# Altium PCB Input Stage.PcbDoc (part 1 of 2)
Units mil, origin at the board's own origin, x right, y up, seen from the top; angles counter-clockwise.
Board outline 5000 x 8750 mil, 6 copper layers (Top Layer, Layer 1, Layer 2, Layer 3, Layer 4, Bottom Layer), stack 91 mil thick; 55 components, 34 nets, 272 pads, 68 vias.
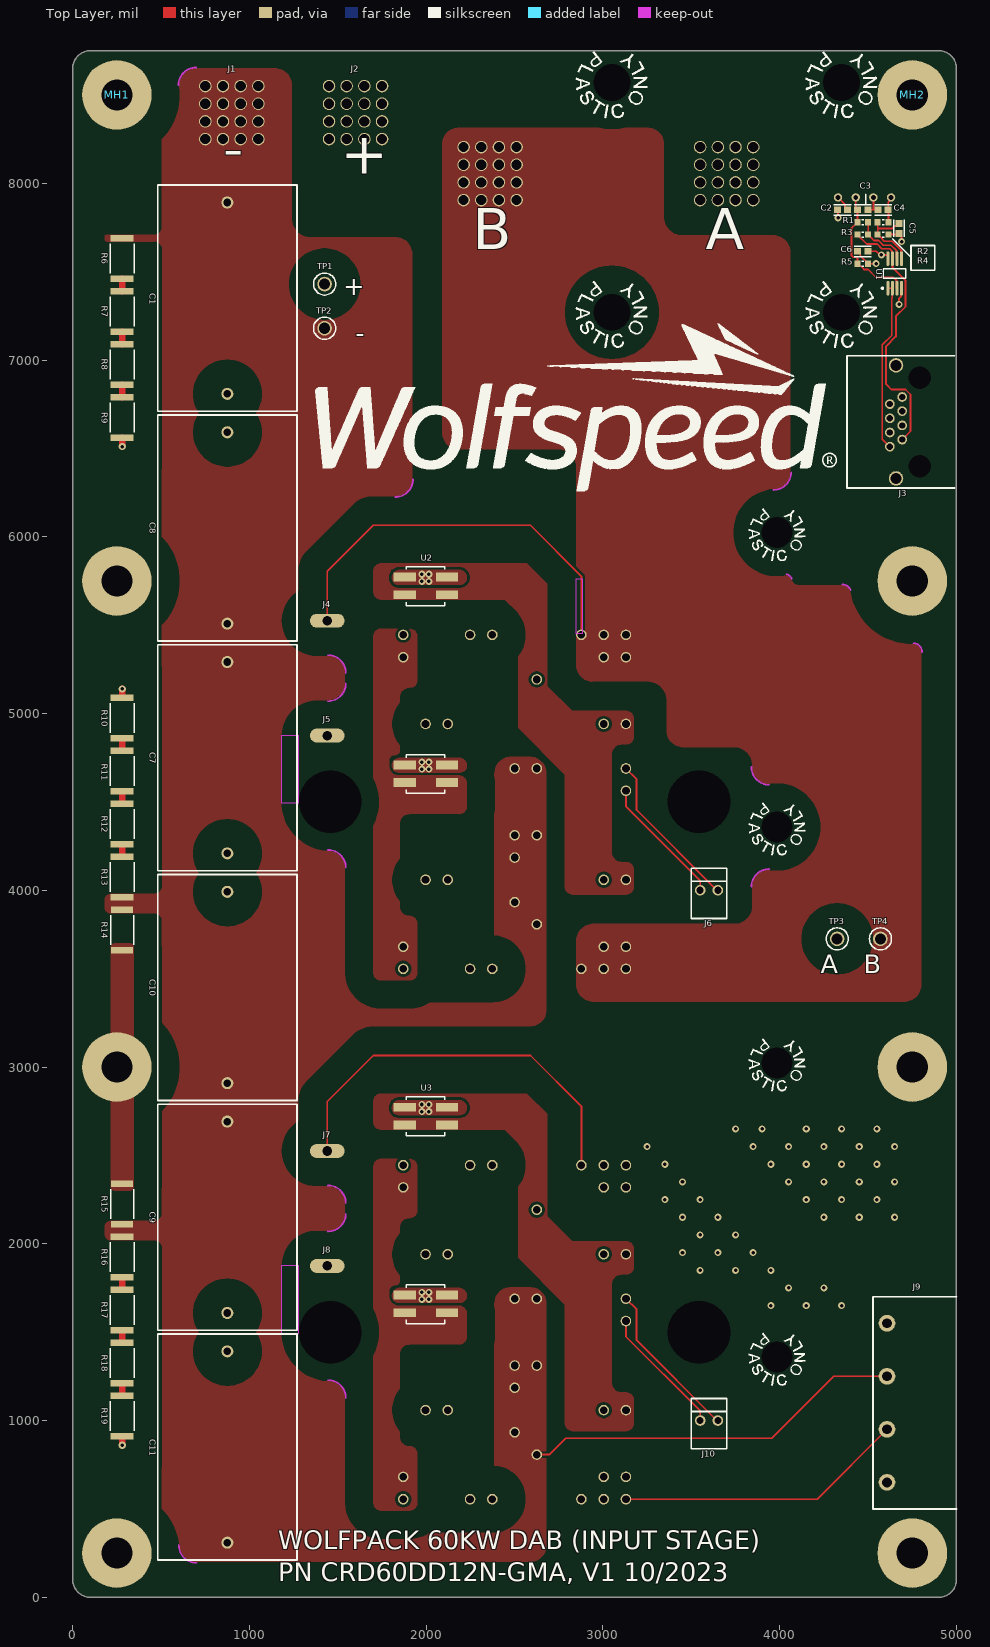
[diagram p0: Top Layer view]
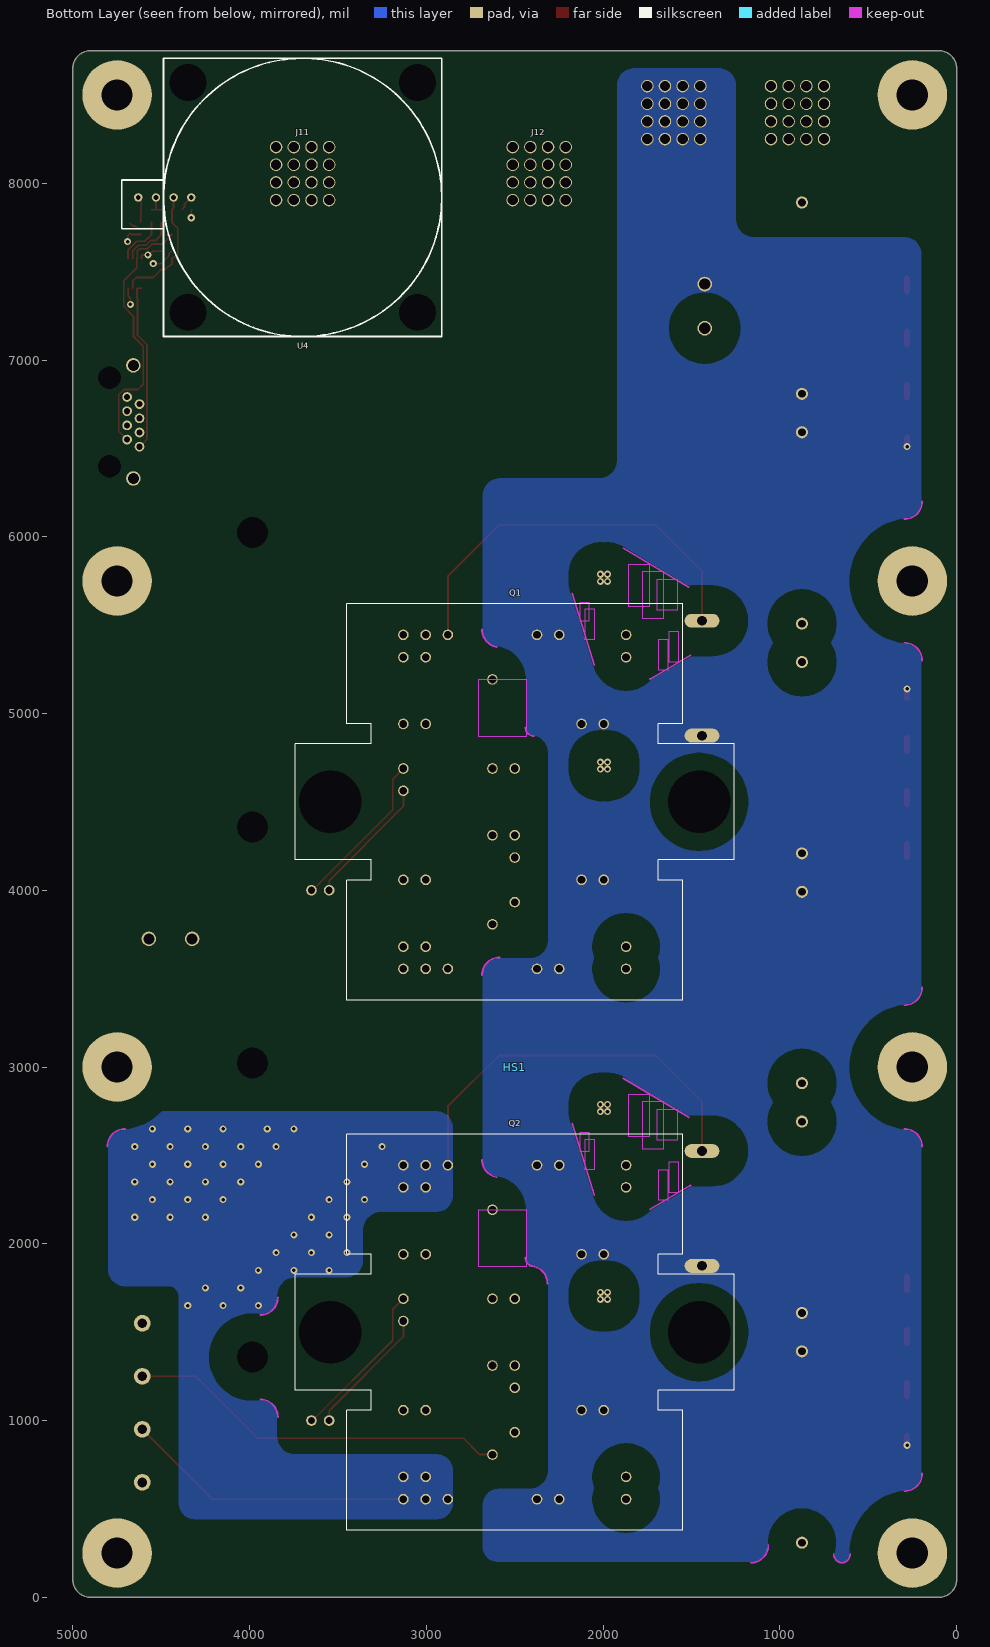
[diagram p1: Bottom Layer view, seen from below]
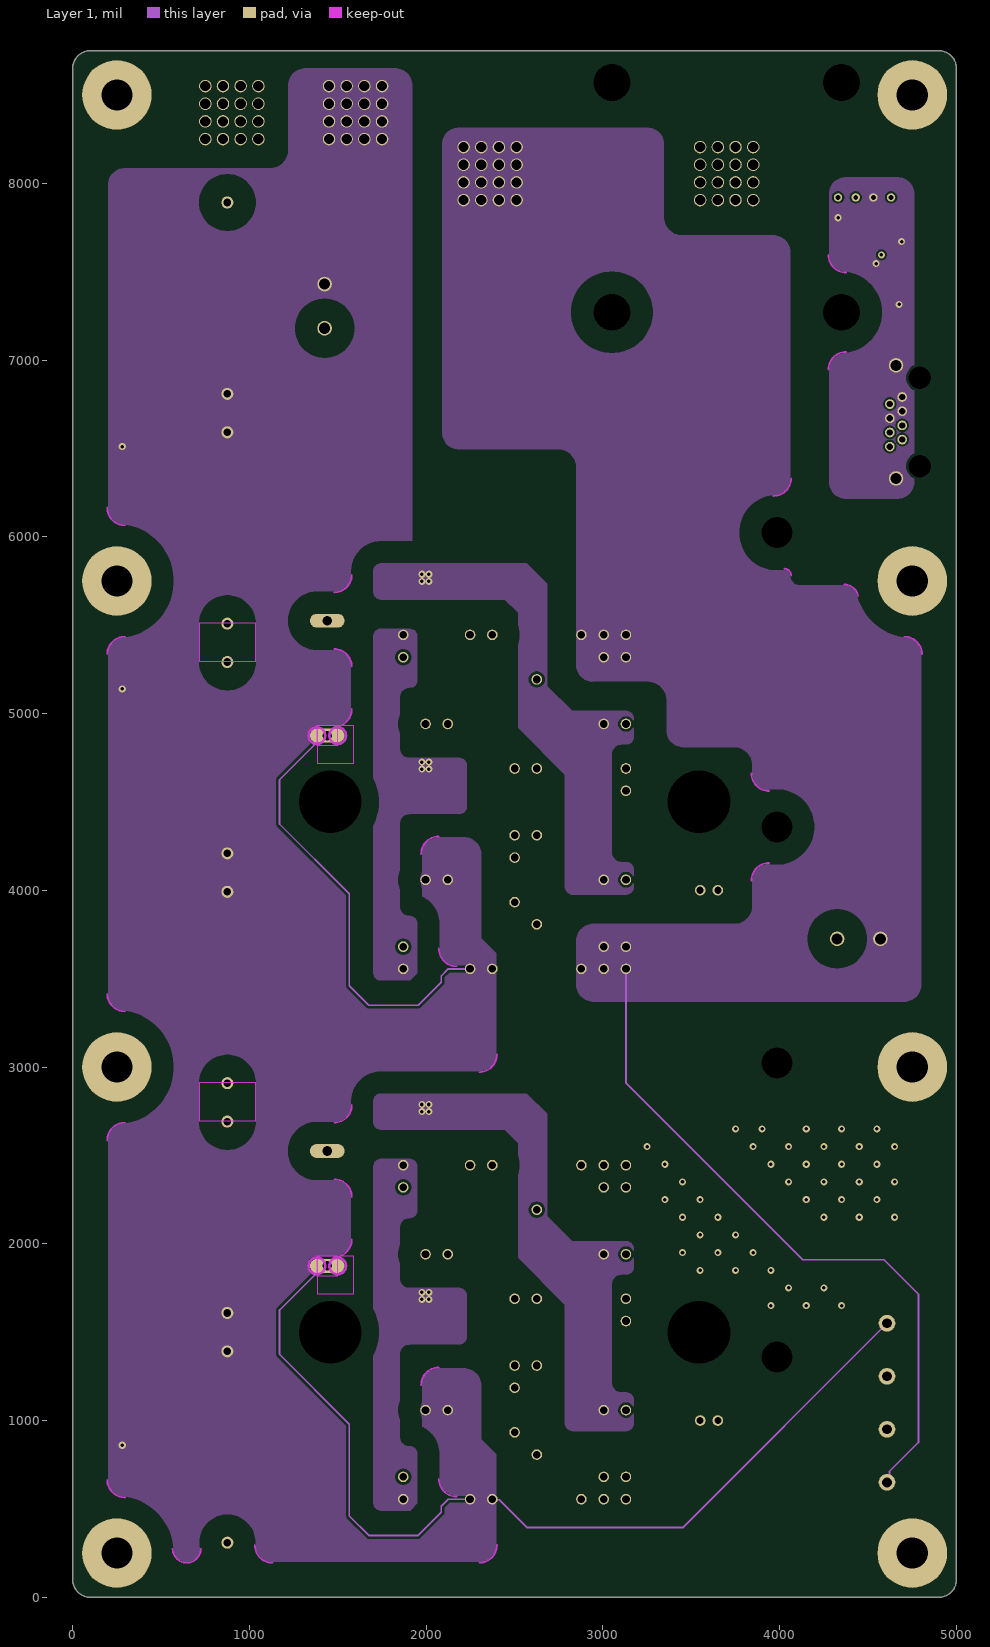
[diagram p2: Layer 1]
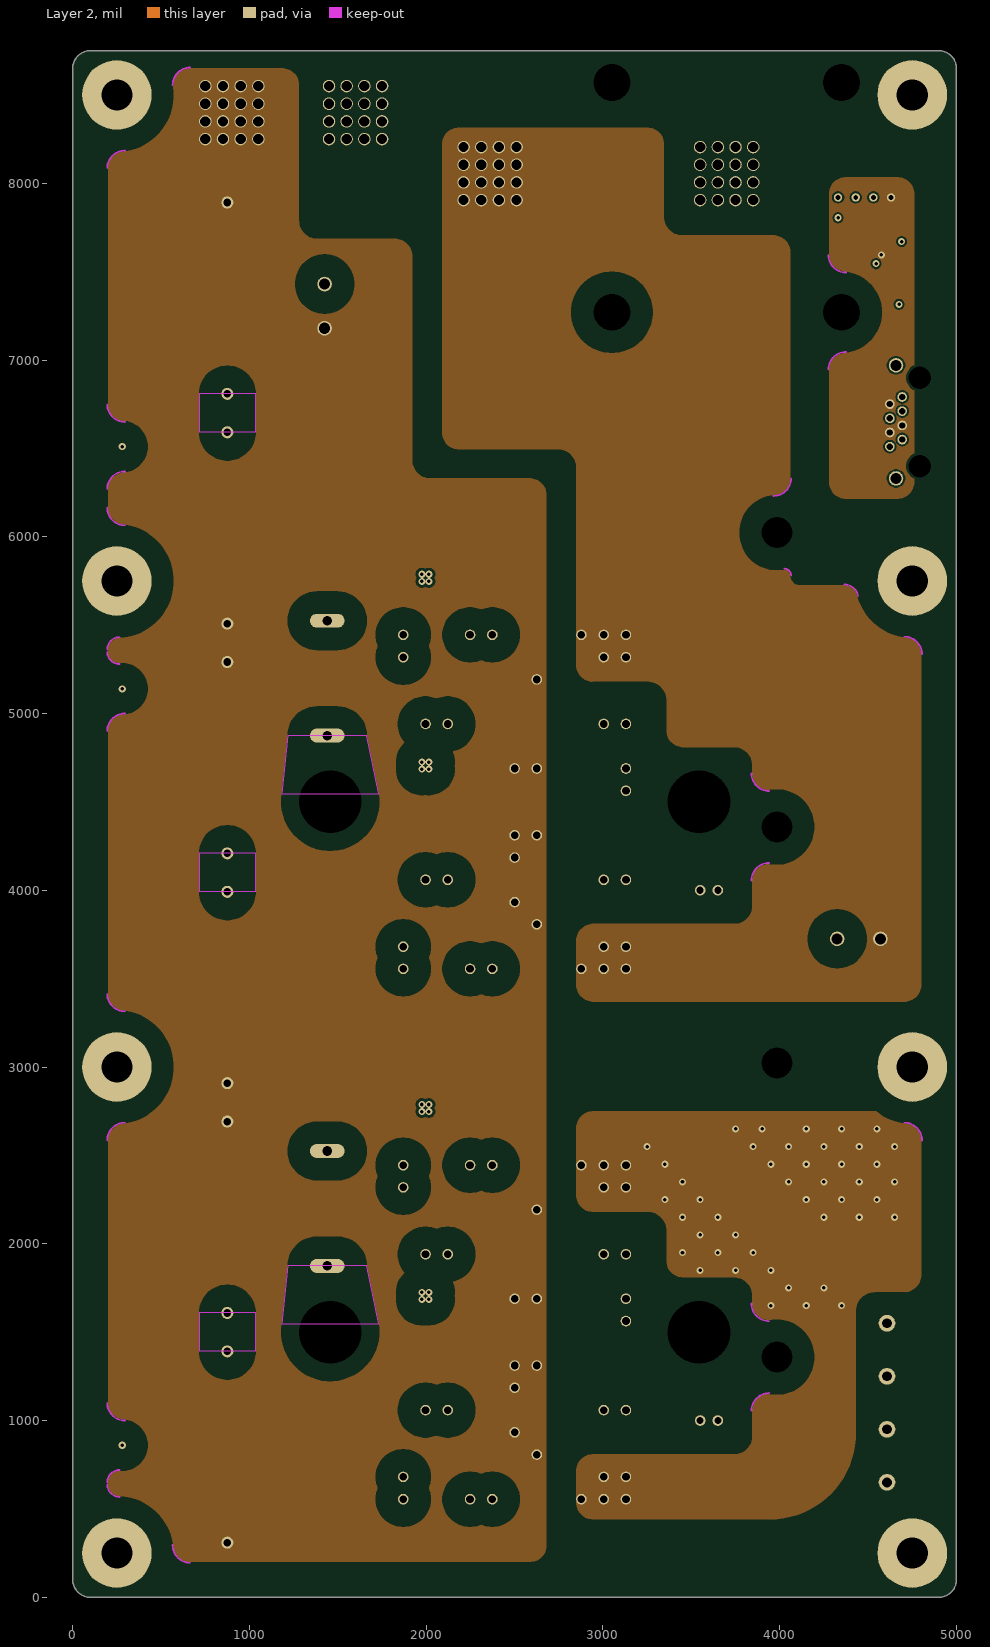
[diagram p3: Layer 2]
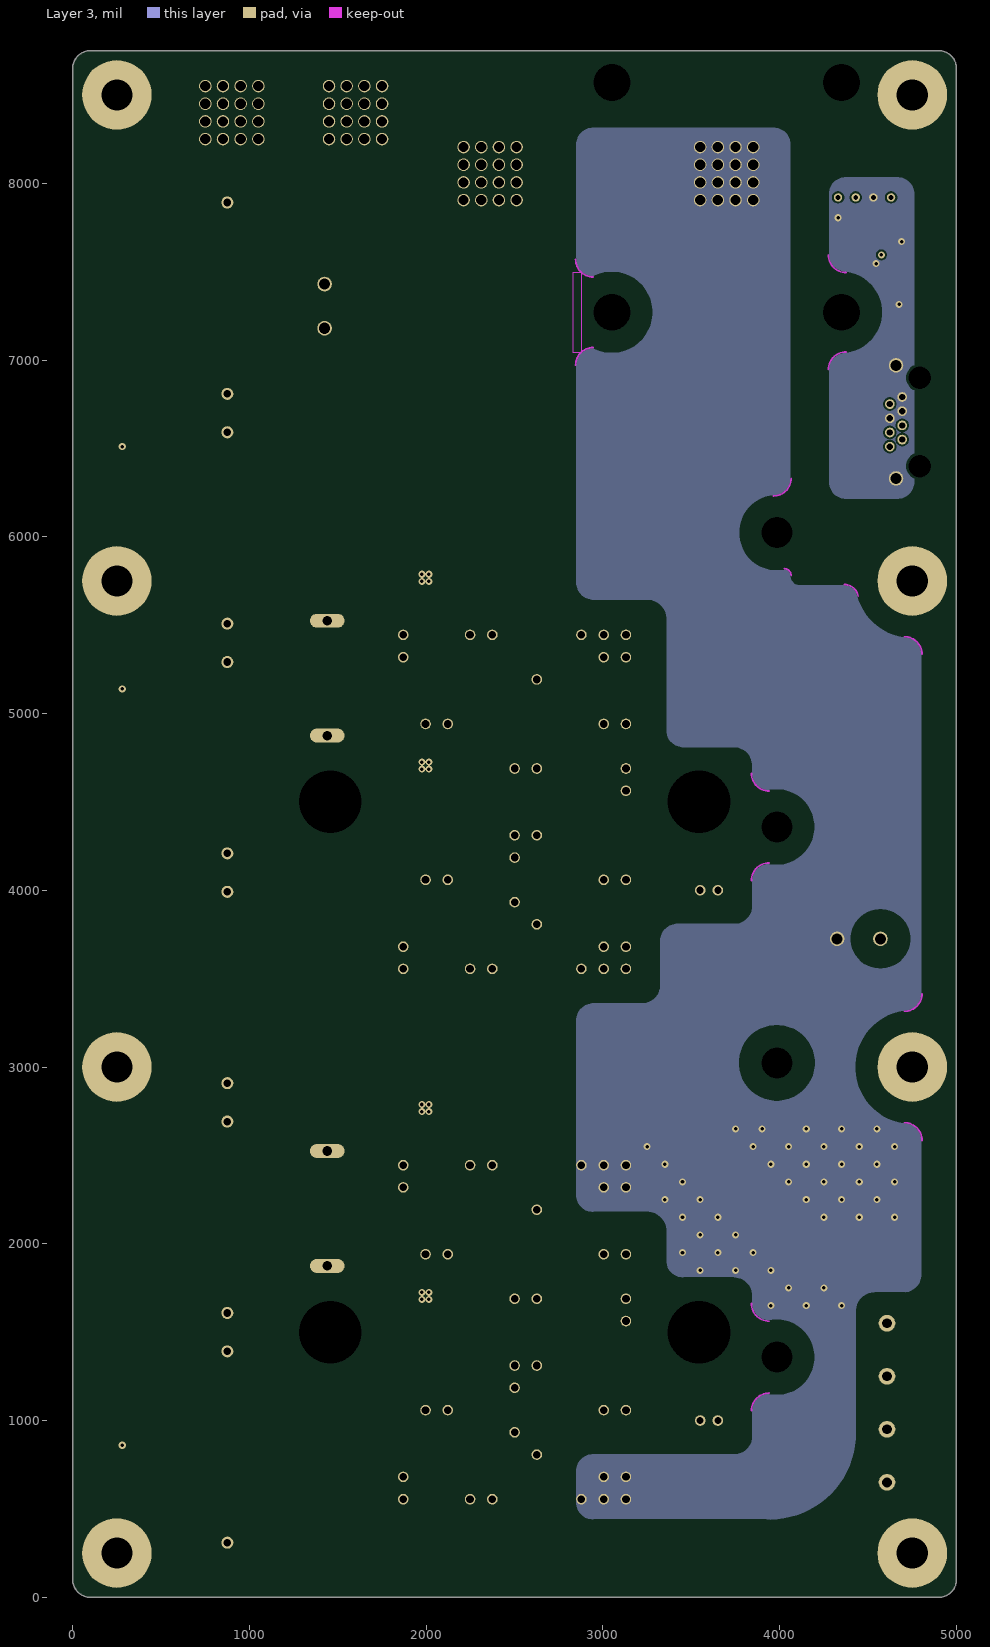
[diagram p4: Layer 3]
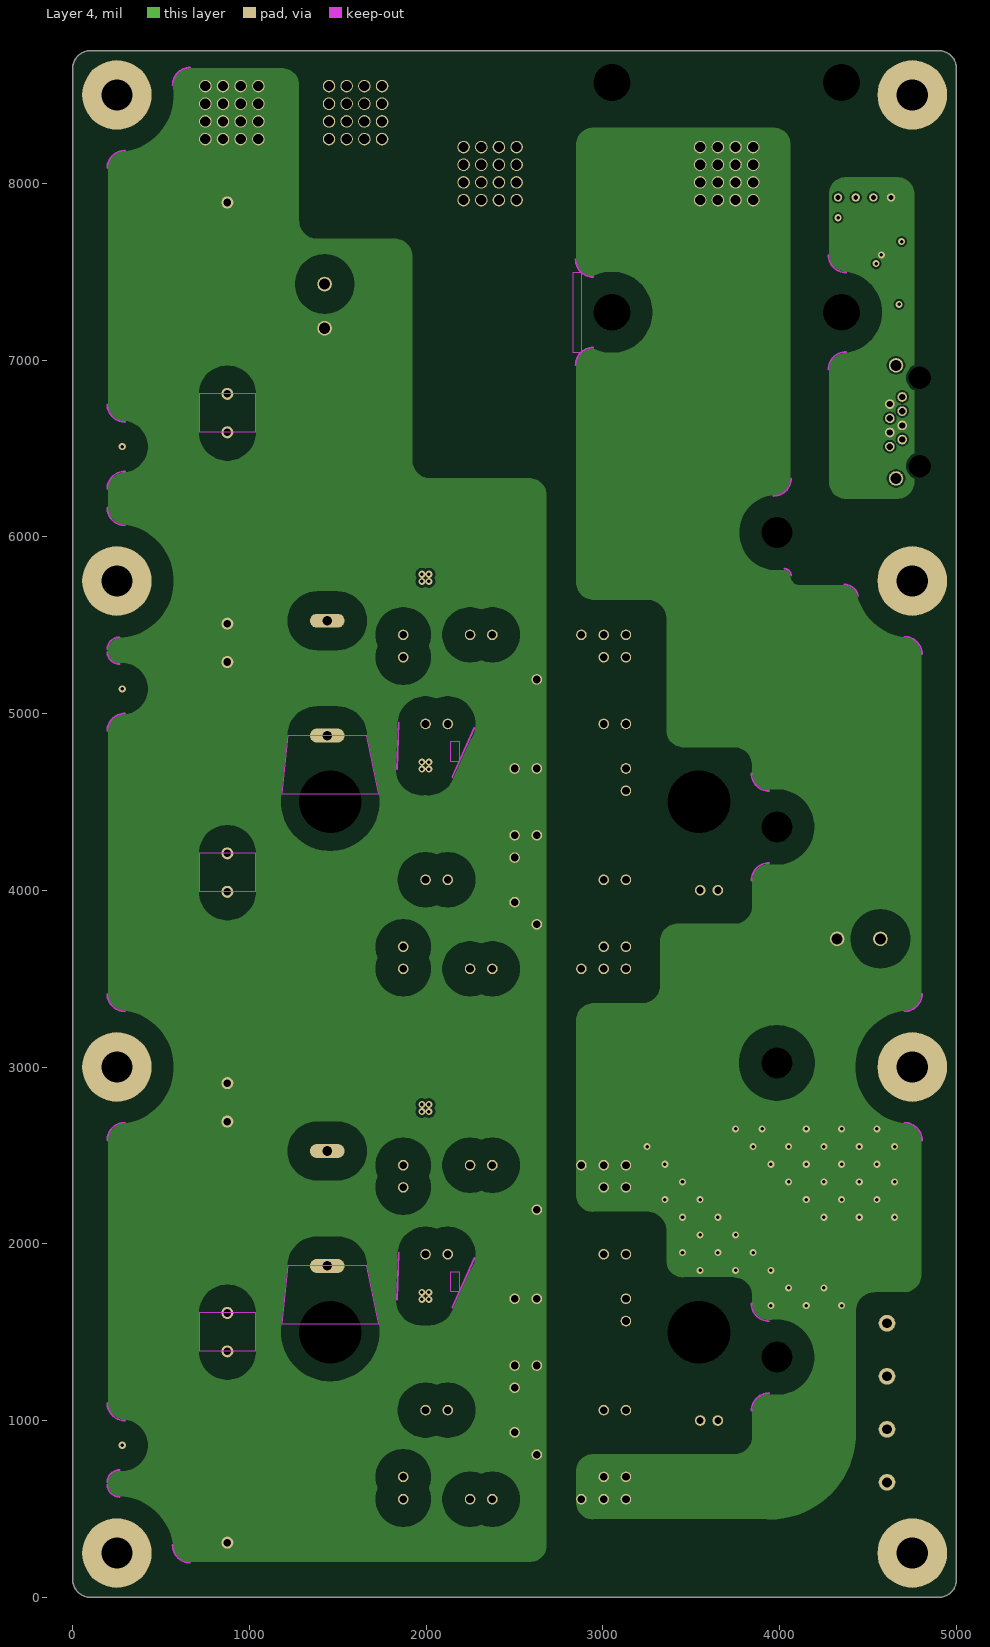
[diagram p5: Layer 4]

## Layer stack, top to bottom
Top Solder: solder mask 1, SM-001, Dk 4
Top Layer: signal copper 8.268
Dielectric 1: prepreg 12.2, PP-006, Dk 4.1
Layer 1: signal copper 8.268
Dielectric 2: prepreg 2.8, PP-006, Dk 4.1
Layer 2: signal copper 8.268
Dielectric 3: dielectric 11.392, FR-4, Dk 4.8
Layer 3: signal copper 8.268
Dielectric 4: prepreg 2.8, PP-006, Dk 4.1
Layer 4: signal copper 8.268
Dielectric 5: prepreg 12.2, PP-006, Dk 4.1
Bottom Layer: signal copper 8.268
Bottom Solder: solder mask 1, SM-001, Dk 4

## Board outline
0,100 0,8650 cw(c100,8650) 100,8750 4900,8750 cw(c4900,8650) 5000,8650 5000,100 cw(c4900,100) 4900,0 100,0 cw(c100,100)

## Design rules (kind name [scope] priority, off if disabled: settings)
Clearance Keepout [IsKeepOut] p1: gap=0 ignorepadtopadclearanceinfootprint=TRUE
Clearance "SENSE CLASS" [InNetClass('SENSE CLASS') vs InNetClass('SENSE CLASS')] p2: gap=10 ignorepadtopadclearanceinfootprint=TRUE except(0: Arc-Hole Track-Hole SMDPad-Hole THPad-Hole Via-Hole Fill-Hole Poly-Hole Region-Hole Text-Hole)
Clearance "A CLASS" [InNetClass('A CLASS') vs InNetClass('A CLASS')] p3: gap=15 ignorepadtopadclearanceinfootprint=TRUE except(0: Arc-Hole Track-Hole SMDPad-Hole THPad-Hole Via-Hole Fill-Hole Poly-Hole Region-Hole Text-Hole)
Clearance "B CLASS" [InNetClass('B CLASS') vs InNetClass('B CLASS')] p4: gap=15 ignorepadtopadclearanceinfootprint=TRUE except(0: Arc-Hole Track-Hole SMDPad-Hole THPad-Hole Via-Hole Fill-Hole Poly-Hole Region-Hole Text-Hole)
Clearance "DC- CLASS" [InNetClass('DC- CLASS') vs InNetClass('DC- CLASS')] p5: gap=15 ignorepadtopadclearanceinfootprint=TRUE except(0: Arc-Hole Track-Hole SMDPad-Hole THPad-Hole Via-Hole Fill-Hole Poly-Hole Region-Hole Text-Hole)
Clearance "DC+ CLASS" [InNetClass('DC+ CLASS') vs InNetClass('DC+ CLASS')] p6: gap=15 ignorepadtopadclearanceinfootprint=TRUE except(0: Arc-Hole Track-Hole SMDPad-Hole THPad-Hole Via-Hole Fill-Hole Poly-Hole Region-Hole Text-Hole)
Clearance "Module Mounting Holes" [HoleDiameter > 350] p7: gap=100 ignorepadtopadclearanceinfootprint=TRUE
Clearance "Ethernet Mounting Holes" [HoleDiameter = 127.953] p8: gap=15 ignorepadtopadclearanceinfootprint=TRUE except(0: Arc-Hole Track-Hole SMDPad-Hole THPad-Hole Via-Hole Fill-Hole Poly-Hole Region-Hole Text-Hole)
Clearance "Internal Clearance" [InLayerClass('InnerLayers')] p9: gap=126 ignorepadtopadclearanceinfootprint=TRUE except(0: Arc-Hole Track-Hole SMDPad-Hole THPad-Hole Via-Hole Fill-Hole Poly-Hole Region-Hole Text-Hole)
Clearance "External Clearance" [All] p10: gap=160 ignorepadtopadclearanceinfootprint=TRUE except(0: Arc-Hole Track-Hole SMDPad-Hole THPad-Hole Via-Hole Fill-Hole Poly-Hole Region-Hole Text-Hole)
Height [All] p1: minheight=0 maxheight=2000 prefheight=500
HoleSize [All] p1: absolutevalues=TRUE maxlimit=500 minlimit=1 maxpercent=80.000 minpercent=20.000
MinimumSolderMaskSliver [All] p1: minsoldermaskwidth=5
PolygonConnect [All] p1: connectstyle=Direct reliefconductorwidth=10 reliefentries=4 polygonreliefangle="90 Angle" airgapwidth=10
RoutingVias [All] p1: holewidth=28 width=50 viastyle="Through Hole" minholewidth=28 minwidth=50 maxholewidth=28 maxwidth=50
SilkToSolderMaskClearance [IsPad] p1: minsilkscreentomaskgap=3.5 clearancetoexposedcopper=TRUE
SolderMaskExpansion [All] p1: expansion=4 istentingtop=FALSE
Width [All] p1: maxlimit=250 minlimit=10 preferedwidth=15
26 further rules are at their usual default settings.

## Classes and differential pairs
net class "SENSE CLASS": +2.5V +5V GND NetC2_1 NetJ10_3 NetJ10_4 NetJ10_5 NetJ10_6 NetR1_2 NetU3_4 OUT_N OUT_P SENSE
net class "DC+ CLASS": DC+
net class "DC- CLASS": DC- G_A_LS G_B_LS NTC_A+ NTC_A- NTC_B+ NTC_B- S_A_LS S_B_LS
net class "B CLASS": AC_B G_B_HS S_B_HS
net class "A CLASS": AC_A G_A_HS S_A_HS

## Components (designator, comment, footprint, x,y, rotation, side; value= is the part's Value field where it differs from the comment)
C1 "C4AQQBU4500A11J" C4AQQBU4500A11J 875,7350 r90 top value=5μF (schematic designator C6)
C2 "CGA3E3X7S2A473K080AB" FP-C0603C-CF-IPC_B 4355,7850 r180 top value=47nF (schematic designator C12)
C3 "C0603C472K5RACAUTO" FP-C0603C-CF-IPC_B 4470,7850 r0 top value=4.7nF (schematic designator C9)
C4 "CGA3E3X7S2A473K080AB" FP-C0603C-CF-IPC_B 4585,7850 r180 top value=47nF (schematic designator C10)
C5 "CL10B104KB8NNWC" FP-C0603C-CF-IPC_B 4675,7745 r270 top value=100nF (schematic designator C11)
C6 "CL10B104KB8NNWC" FP-C0603C-CF-IPC_B 4470,7615 r180 top value=100nF (schematic designator C8)
C7 "C4AQQBU4500A11J" C4AQQBU4500A11J 875,6050 r270 top value=5μF (schematic designator C4)
C8 "C4AQQBU4500A11J" C4AQQBU4500A11J 875,4750 r90 top value=5μF (schematic designator C5)
C9 "C4AQQBU4500A11J" C4AQQBU4500A11J 875,3450 r270 top value=5μF (schematic designator C3)
C10 "C4AQQBU4500A11J" C4AQQBU4500A11J 875,2150 r90 top value=5μF (schematic designator C2)
C11 "C4AQQBU4500A11J" C4AQQBU4500A11J 875,850 r270 top value=5μF (schematic designator C1)
HS1 "120456" 120456 2500,3000 r90 bottom locked value=N/A
J1 "7461095" "7461095_chemical surface" 900,8400 r0 top value=N/A (schematic designator J5)
J2 "7461095" "7461095_chemical surface" 1600,8400 r0 top value=N/A (schematic designator J4)
J3 "2-406541-2" 2-406541-2 4793,6650 r90 top value=N/A (schematic designator J10)
J4 "735187-2" 735187-2 1440,5525 r90 top value=N/A (schematic designator J9)
J5 "735187-2" 735187-2 1440,4875 r90 top value=N/A (schematic designator J8)
J6 "0022280021" 0022280021 3600,4000 r0 top value=N/A (schematic designator J16)
J7 "735187-2" 735187-2 1440,2525 r90 top value=N/A
J8 "735187-2" 735187-2 1440,1875 r90 top value=N/A (schematic designator J6)
J9 "1728879" 1728879 4607,1100 r90 top locked value=N/A (schematic designator J2)
J10 "0022280021" 0022280021 3600,1000 r0 top value=N/A (schematic designator J15)
J11 "7461095" "7461095_chemical surface" 3700,8055 r180 bottom value=N/A (schematic designator J1)
J12 "7461095" "7461095_chemical surface" 2361.42,8055 r180 bottom value=N/A (schematic designator J3)
MH1 "MH_M4_P" MH_M4_P#1 250,8700 r0 top (schematic designator MH5)
MH2 "MH_M4_P" MH_M4_P#2 4850,8700 r0 top (schematic designator MH3)
Q1 "CAB006M12GM3" GM3_CRW_MH 2500,4500 r270 bottom locked value=N/A (schematic designator Q2)
Q2 "CAB006M12GM3" GM3_CRW_MH 2500,1500 r270 bottom locked value=N/A (schematic designator Q1)
R1 "RG1608P-103-BT5" FP-AC0603-IPC_B 4470,7780 r0 top value=10kΩ (schematic designator R3)
R2 "RG1608P-103-BT5" FP-AC0603-IPC_B 4585,7780 r0 top value=10kΩ (schematic designator R4)
R3 "RG1608P-103-BT5" FP-AC0603-IPC_B 4470,7710 r180 top value=10kΩ (schematic designator R1)
R4 "RG1608P-103-BT5" FP-AC0603-IPC_B 4585,7710 r180 top value=10kΩ (schematic designator R5)
R5 "RG1608P-103-BT5" FP-AC0603-IPC_B 4470,7545 r180 top value=10kΩ
R6 "CRGP2512F220K" FP-CRGP2512-IPC_C 280,7575 r90 top value=220kΩ
R7 "CRGP2512F220K" FP-CRGP2512-IPC_C 280,7275 r90 top value=220kΩ (schematic designator R14)
R8 "CRGP2512F220K" FP-CRGP2512-IPC_C 280,6975 r90 top value=220kΩ (schematic designator R11)
R9 "CRGP2512F220K" FP-CRGP2512-IPC_C 280,6675 r90 top value=220kΩ (schematic designator R8)
R10 "CRGP2512F220K" FP-CRGP2512-IPC_C 280,4975 r270 top value=220kΩ (schematic designator R6)
R11 "CRGP2512F220K" FP-CRGP2512-IPC_C 280,4675 r270 top value=220kΩ (schematic designator R9)
R12 "CRGP2512F220K" FP-CRGP2512-IPC_C 280,4375 r270 top value=220kΩ
R13 "CRGP2512F220K" FP-CRGP2512-IPC_C 280,4075 r270 top value=220kΩ (schematic designator R15)
R14 "RC2512JK-070RL" FP-RC2512-0_65-IPC_C 280,3775 r270 top value=0Ω (schematic designator R18)
R15 "RC2512JK-070RL" FP-RC2512-0_65-IPC_C 280,2225 r90 top value=0Ω (schematic designator R19)
R16 "CRGP2512F220K" FP-CRGP2512-IPC_C 280,1925 r90 top value=220kΩ
R17 "CRGP2512F220K" FP-CRGP2512-IPC_C 280,1625 r90 top value=220kΩ (schematic designator R13)
R18 "CRGP2512F220K" FP-CRGP2512-IPC_C 280,1325 r90 top value=220kΩ (schematic designator R10)
R19 "CRGP2512F220K" FP-CRGP2512-IPC_C 280,1025 r90 top value=220kΩ (schematic designator R7)
TP1 "5010" KSTN-5010_V 1425,7430 r0 top value=RED
TP2 "5011" KSTN-5011_V 1425,7180 r0 top value=BLACK
TP3 "5012" KSTN-5012_V 4325,3725 r0 top value=WHITE
TP4 "5014" KSTN-5014_V 4570,3725 r0 top value=YELLOW
U1 "AD8616ARMZ-REEL" ADI-RM-8_M 4650,7490 r90 top value=N/A (schematic designator U4)
U2 "WolfPack Dual Gate Driver Board Assembly" "WolfPack Dual Gate Driver Board Assembly-Footprint-3" 1800,5190 r270 top locked value=N/A
U3 "WolfPack Dual Gate Driver Board Assembly" "WolfPack Dual Gate Driver Board Assembly-Footprint-3" 1800,2190 r270 top locked value=N/A (schematic designator U1)
U4 "HTFS200-P/SP2" "HTFS 200-P (No Hole)" 3700,7920 r270 bottom locked value=N/A (schematic designator U3)

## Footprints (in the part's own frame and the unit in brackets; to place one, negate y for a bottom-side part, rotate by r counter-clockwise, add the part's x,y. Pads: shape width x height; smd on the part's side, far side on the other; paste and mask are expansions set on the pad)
2-406541-2 [mm] "CONN MOD JACK R/A 8P8C SHLD"
  round 1.398 hole 0.89: 1(3.58,2.54) 2(2.56,4.32) 3(1.54,2.54) 4(0.52,4.32) 5(-0.5,2.54) 6(-1.52,4.32) 7(-2.54,2.54) 8(-3.56,4.32)
  round 2.087 hole 1.57: 9(8.13,3.43) 10(-8.13,3.43)
  round 0 hole 3.25 unplated: 11(-6.35,0) 11(6.35,0)
  silkscreen extent -9.5,-5 9.5,10.47, body extent -8.13,-5.28 8.13,10.47, height 13.4
120456 [mm]
  round 10 hole 4.5: 1(-69.85,57.15) 2(0,57.15) 3(69.85,57.15) 4(69.85,-57.15) 5(0,-57.15) 6(-69.85,-57.15)
  body extent -127.01,-63.5 101.59,63.5, height 27.24
735187-2 [mm] "CONN QC TAB 0.110 SOLDER"
  oval 2x5 hole 1.4: 1(0,0)
  body extent -0.39,-2.15 0.25,2.15, height 8.62
1728879 [mm] "TERM BLOCK HDR 4POS 90DEG 7.62MM"
  round 2.4 hole 1.4: 1(-11.43,0) 2(-3.81,0) 3(3.81,0) 4(11.43,0)
  silkscreen extent -15.24,-10 15.24,2, body extent -15.24,-10 15.19,2, height 8.57
"7461095_chemical surface" [mm] "M4, blind 4mm"
  round 1.8 hole 1.475: 1(-3.81,-3.81) 1(-3.81,-1.27) 1(-3.81,1.27) 1(-3.81,3.81) 1(-1.27,-3.81) 1(-1.27,-1.27) 1(-1.27,1.27) 1(-1.27,3.81) 1(1.27,-3.81) 1(1.27,-1.27) 1(1.27,1.27) 1(1.27,3.81) 1(3.81,-3.81) 1(3.81,-1.27) 1(3.81,1.27) 1(3.81,3.81)
  body extent -4.5,-4.5 4.5,4.5, height 7
0022280021 [mil] "CONN HEADER VERT 2POS 2.54MM"
  round 60 hole 40.16: 1(-50,0) 2(50,0)
  silkscreen extent -100,-160 100,124, body extent -100,-160 100,124, height 422
ADI-RM-8_M [mm] "SOP, 8-Leads, Body 3x3mm, Pitch 0.65mm, IPC Low Density"
  oval 2.1x0.45 smd: 1(-2.125,0.975) 2(-2.125,0.325) 3(-2.125,-0.325) 4(-2.125,-0.975) 5(2.125,-0.975) 6(2.125,-0.325) 7(2.125,0.325) 8(2.125,0.975)
  silkscreen extent -2.25,-1.6 0.67,1.87, body extent -1.6,-1.6 1.6,1.6, height 1.1
C4AQQBU4500A11J [mm]
  round 1.735 hole 1.1: 1(-13.75,0) 2(13.75,0)
  silkscreen extent -16.25,-10 16.25,10, body extent -16,-9.65 16,9.65, height 29.2
FP-AC0603-IPC_B [mil]
  rect 33.81x35.91 smd paste+0 mask+0: 1(-30.58,0) 2(30.58,0)
  silkscreen extent -6,-14 6,14, body extent -31,-18 31,18, height 20
FP-C0603C-CF-IPC_B [mil]
  rect 39.63x37.73 smd paste+0 mask+0: 1(-28.58,0) 2(28.58,0)
  silkscreen extent -48,-30 48,30, body extent -58,-29 58,29, height 35
FP-CRGP2512-IPC_C [mil]
  rect 37.72x130.17 smd paste+0 mask+0: 1(-114.25,0) 2(114.25,0)
  silkscreen extent -84,-67 84,67, body extent -137,-71 137,71, height 10
FP-RC2512-0_65-IPC_C [mil]
  rect 37.72x124.34 smd paste+0 mask+0: 1(-114.25,0) 2(114.25,0)
  silkscreen extent -84,-64 84,64, body extent -137,-68 137,68, height 10
GM3_CRW_MH [mm]
  round 0 hole 9 unplated: 2(0,-26.5) 2(0,26.5)
  round 1.524 hole 1.1: AC_1(-24,-9.6) AC_2(24,-9.6) AC_3(-24,-12.8) AC_4(-20.8,-12.8) AC_5(20.8,-12.8) AC_6(24,-12.8) AC_7(-24,-16) AC_8(-20.8,-16) AC_9(20.8,-16) AC_10(24,-16) DC+_1(-11.2,12.8) DC+_2(11.2,12.8) DC+_3(-11.2,9.6) DC+_4(11.2,9.6) DC+_5(-24,6.4) DC+_6(24,6.4) DC+_7(-24,3.2) DC+_8(24,3.2) DC-_1(-4.8,0) DC-_2(4.8,0) DC-_3(8,0) DC-_4(14.4,0) DC-_5(-17.6,-3.2) DC-_6(-4.8,-3.2) DC-_7(4.8,-3.2) DC-_8(17.6,-3.2) G1_1(-20.8,16) G1_2(20.8,16) G2_1(-11.2,-16) G2_2(11.2,-16) NTC1(-4.8,-16) NTC2(-1.6,-16) S1_1(-24,16) S1_2(24,16) S2_1(-11.2,-12.8) S2_2(11.2,-12.8)
  silkscreen extent -28.47,-31.52 28.47,31.52, body extent -28.35,-31.4 28.35,31.4, height 12.08
"HTFS 200-P (No Hole)" [mm]
  round 1.208 hole 0.7: 1(0,-23.62) 2(0,-21.08) 3(0,-18.54) 4(0,-16)
  round 0 hole 5.3 unplated: MH1(-16.5,16.5) MH2(16.5,16.5) MH3(16.5,-16.5) MH4(-16.5,-16.5)
  silkscreen extent -20,-26 20,20, body extent -20,-26 20,20, height 16.5
KSTN-5010_V [mm] "Test Point, Dia 3.17mm"
  round 2.1 hole 1.6: 1(0,0)
  silkscreen extent -1.59,-1.58 1.59,1.58, body extent -1.59,-1.59 1.59,1.59, height 8.13
KSTN-5011_V [mm] "Test Point, Dia 3.17mm"
  round 2.1 hole 1.6: 1(0,0)
  silkscreen extent -1.59,-1.58 1.59,1.58, body extent -1.59,-1.59 1.59,1.59, height 8.13
KSTN-5012_V [mm] "Test Point, Dia 3.17mm"
  round 2.1 hole 1.6: 1(0,0)
  silkscreen extent -1.59,-1.58 1.59,1.58, body extent -1.59,-1.59 1.59,1.59, height 8.13
KSTN-5014_V [mm] "Test Point, Dia 3.17mm"
  round 2.1 hole 1.6: 1(0,0)
  silkscreen extent -1.59,-1.58 1.59,1.58, body extent -1.59,-1.59 1.59,1.59, height 8.13
MH_M4_P#1 [mm] "M4 plated mounting hole"
  round 10 hole 4.5: 1(0,-5.08)
MH_M4_P#2 [mm] "M4 plated mounting hole"
  round 10 hole 4.5: 1(-2.54,-5.08)
"WolfPack Dual Gate Driver Board Assembly-Footprint-3" [mil]
  rect 50x125 smd: 1A(480.53,316.96) 1B(-582.47,316.96) 2A(580.53,316.96) 2B(-482.47,316.96) 3A(480.53,78.46) 3B(-582.47,78.46) 4A(580.53,78.46) 4B(-482.47,78.46)
  round 0 hole 175 unplated: A46(-833.49,2183.63) A46(831.55,2183.63)
  silkscreen extent -641,86 642,306, body extent -1237,15 1000,2365, height 951

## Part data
C1 C7 C8 C9 C10 C11: "CAP FILM 5UF 5% 1.1KVDC RADIAL", Capacitance=5μF, Case/Package=RADIAL, Dielectric Material=PP, ESR (Equivalent Series Resistance)=9.1mR, Manufacturer=KEMET, Max Operating Temperature=105°C, Min Operating Temperature=-40°C, Ratings=AEC-Q200, Supplier Part Number 1=80-C4AQQBU4500A11J, TOLERANCE=5%, Voltage Rating (DC)=1.1kV
C2 C4: "CAP CER 0.047UF 100V X7S 0603", Case Code (Imperial)=0603, Case Code (Metric)=1608, Dielectric=X7S, Manufacturer=TDK, Max Operating Temperature=125°C, Min Operating Temperature=-55°C, Package Quantity=4000, Ratings=AEC-Q200, TOLERANCE=10%, Voltage Rating=100V
C3: library part CMP-001-00119-9, "CAP CER 4700PF 50V X7R 0603", Capacitor Type=Ceramic, Case/Package=0603, Manufacturer=KEMET, Max Operating Temperature=125°C, Min Operating Temperature=-55°C, Temperature Coefficient=X7R, TOLERANCE=10%, Voltage Rating=50V
C5 C6: library part CMP-00017-3, "CAP CER 0.1UF 50V X7R 0603", Capacitor Type=Ceramic, Case/Package=0603, Manufacturer=SAMSUNG, Max Operating Temperature=125°C, Min Operating Temperature=-55°C, Temperature Coefficient=X7R, TOLERANCE=10%, Voltage Rating=50V
HS1: "COLD PLATE HEAT SINK EXPOSED", Case/Package=N/A, Manufacturer=WAKEFIELD, Supplier Part Number 1=345-1425-ND
J1 J2 J11 J12: library part CMP-03913-18187404-1, "TERM REDCUBE M4 16PIN PCB", Case/Package=N/A, Current Rating=180A, Manufacturer=WURTH, Max Operating Temperature=150°C, Min Operating Temperature=-55°C
J3: "CONN MOD JACK R/A 8P8C SHLD", Case/Package=N/A, Manufacturer=TE
J4 J5 J7 J8: "CONN QC TAB 0.110 SOLDER", Case/Package=N/A, Manufacturer=TE
J6 J10: "CONN HEADER VERT 2POS 2.54MM", Case/Package=N/A, Manufacturer=MOLEX, Supplier Part Number 1=WM19476-ND
J9: "TERM BLOCK HDR 4POS 90DEG 7.62MM", Case/Package=N/A, Manufacturer="PHEONIX CONTACT"
Q1 Q2: "SIC 2N-CH 1200V", Case/Package=GMA, Manufacturer=WOLFSPEED
R1 R2 R3 R4 R5: library part CMP-009-00206-2, "RES SMD 10K OHM 0.1% 1/10W 0603", Case/Package=0603, Manufacturer=SUSUMU, Manufacturer Part Number=RG1608P-103-B-T5, Max Operating Temperature=155°C, Min Operating Temperature=-55°C, POWER=0.1W, TOLERANCE=0.1%, Voltage Rating=75V
R6 R7 R8 R9 R10 R11 R12 R13 R16 R17 R18 R19: library part CMP-03211-002966-1, "RES 220K OHM 1% 2W 2512", Ambient Temperature Range High=+70°C, Case/Package=2512, Manufacturer=TE, Power Rating=2W, Resistance=220KΩ, Temperature="-55°C to +155°C", Temperature Coefficient=±100ppm/°C, Temperature Range High=+155°C, Temperature Range Low=-55°C, TOLERANCE=0.01, Voltage Rating=500V
R14 R15: library part CMP-2000-06974-2, "RES SMD 0 OHM JUMPER 1W 2512", Case Code (Imperial)=2512, Case Code (Metric)=6432, Manufacturer=YAGEO, Max Operating Temperature=155°C, Max Power Dissipation=1W, Min Operating Temperature=-55°C, Package Quantity=4000, Resistance=0Ω, Resistance Tolerance=5%, Resistor Type="Thick Film", Temperature Coefficient=200ppm/°C, Voltage Rating=200V
TP1: library part CMP-1672-00002-4, "PC TEST POINT MULTIPURPOSE RED", Case/Package=N/A, Colour=Red, Manufacturer=KEYSTONE, Package Quantity=100
TP2: library part CMP-1672-00003-4, "PC TEST POINT MULTIPURPOSE BLACK", Case/Package=N/A, Colour=Black, Manufacturer=KEYSTONE, Package Quantity=100
TP3: library part CMP-1672-00004-4, "PC TEST POINT MULTIPURPOSE WHITE", Case/Package=N/A, Colour=White, Manufacturer=KEYSTONE, Package Quantity=100
TP4: library part CMP-1672-00006-4, "PC TEST POINT MULTI PURP YELLOW", Case/Package=N/A, Colour=Yellow, Manufacturer=KEYSTONE, Package Quantity=100
U1: library part CMP-0384-01706-1, "IC CMOS 2 CIRCUIT 8MSOP", Amplifiers Per Package=2, Case/Package=8-TSSOP, Generic Part Number=AD8616, Input Bias Current=200fA, Input Offset Voltage=23uV, Manufacturer=ANALOG
U2 U3: library part CMP-00030-00001-20, "GATE DRIVER BOARD 1700V CAPABLE", Case/Package=N/A, Manufacturer=WOLFSPEED, Manufacturer Part Number=CGD1700HB2M-UNA
U4: library part "HTFS 200-P", "SENSOR CURRENT HALL 200A AC/DC", Case/Package=N/A, Flammability Rating="UL94 V-0", Manufacturer=LEM, Max Operating Temperature=105°C, Max Supply Voltage (DC)=5.25V, Min Operating Temperature=-40°C, Min Supply Voltage (DC)=4.75V, Operating Supply Voltage=5V, Supplier Part Number 1=97K1712

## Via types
v1: diameter 40, hole 20, Top Layer to Bottom Layer, tented both sides, 68 vias

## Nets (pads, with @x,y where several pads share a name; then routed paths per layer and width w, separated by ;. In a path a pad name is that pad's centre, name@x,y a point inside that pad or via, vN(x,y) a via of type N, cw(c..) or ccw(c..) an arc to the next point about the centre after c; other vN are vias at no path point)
+2.5V: C5.1 R2.1 R4.2 U1.5 | length 423
  Top Layer w10: R2.1@4554.42,7780 4554.42,7742.83 ; C5.1@4675,7773.58 4675,7772.63 4661.14,7758.76 4650.42,7758.76 4636.27,7744.62 4556.21,7744.62 4554.42,7742.83 ; U1.5@4688.39,7573.66 4688.39,7621.61 4637.63,7672.37 4592.37,7672.37 4567.7,7697.04 4566.32,7697.04 4554.42,7708.95 R4.2@4554.42,7710 4554.42,7742.83
+5V: C4.1 C6.1 J3.2 J3.5 J3.6 R2.2 U1.8 U4.1 | length 288.2
  Top Layer w10: C6.1@4498.58,7615 4546.88,7615 4566.88,7595 v1(4575,7595) 4608.05,7595 4611.61,7591.44 U1.8@4611.61,7573.66 ; R2.2@4615.58,7780 4615.58,7848 C4.1@4613.58,7850 4613.58,7893.49 4629.92,7909.84 U4.1@4629.92,7920
AC_A: J7.1 J9.2 J11.1 Q2.AC_1 Q2.AC_2 Q2.AC_3 Q2.AC_4 Q2.AC_5 Q2.AC_6 Q2.AC_7 Q2.AC_8 Q2.AC_9 Q2.AC_10 TP3.1 | length 3917.7
  Top Layer w10: J7.1@1440,2525 1440,2805 1700,3065 2590,3065 2877.95,2777.05 Q2.AC_1@2877.95,2444.88 ; Q2.AC_10@3129.92,555.12 4211.96,555.12 4606.84,950 J9.2@4607,950
  other v1: 3950,1650 4150,1650 4350,1650 4050,1750 4250,1750 3550,1850 3750,1850 3950,1850 3450,1950 3650,1950 3850,1950 3550,2050 3750,2050 3450,2150 3650,2150 4250,2150 4450,2150 4650,2150 3350,2250 3550,2250 4150,2250 4350,2250 4550,2250 3450,2350 4050,2350 4250,2350 4450,2350 4650,2350 3350,2450 3950,2450 4150,2450 4350,2450 4550,2450 3250,2550 3850,2550 4050,2550 4250,2550 4450,2550 4650,2550 3750,2650 3900,2650 4150,2650 4350,2650 4550,2650
AC_B: J4.1 J9.1 J12.1 Q1.AC_1 Q1.AC_2 Q1.AC_3 Q1.AC_4 Q1.AC_5 Q1.AC_6 Q1.AC_7 Q1.AC_8 Q1.AC_9 Q1.AC_10 TP4.1 | length 6211.2
  Top Layer w10: J4.1@1440,5525 1440,5805 1700,6065 2590,6065 2877.95,5777.05 Q1.AC_1@2877.95,5444.88
  Layer 1 w10: Q1.AC_10@3129.92,3555.12 3129.92,2910.08 4130,1910 4590,1910 4785.24,1714.76 4785.24,876.17 4621.32,712.24 4621.32,664.32 J9.1@4607,650
DC+: C1.1 C7.1 C8.1 C9.1 C10.1 C11.1 J2.1 J5.1 J8.1 J9.4 Q1.DC+_1 Q1.DC+_2 Q1.DC+_3 Q1.DC+_4 Q1.DC+_5 Q1.DC+_6 Q1.DC+_7 Q1.DC+_8 Q2.DC+_1 Q2.DC+_2 Q2.DC+_3 Q2.DC+_4 Q2.DC+_5 Q2.DC+_6 Q2.DC+_7 Q2.DC+_8 R9.1 R10.1 R19.1 TP1.1 | length 8027.1
  Top Layer w35: v1(280,860) R19.1@280,910.75 ; R10.1@280,5089.25 v1(280,5140) ; v1(280,6510) R9.1@280,6560.75
  Layer 1 w10: J8.1@1440,1875 1399.55,1875 1367.79,1843.25 1367.79,1822.79 1170,1625 1170,1375 1565,980 1565,460 1675,350 1955,350 2085,480 2085,515 2125.12,555.12 Q2.DC+_6@2248.03,555.12 ; J5.1@1440,4875 1399.55,4875 1367.79,4843.25 1367.79,4822.79 1170,4625 1170,4375 1565,3980 1565,3460 1675,3350 1955,3350 2085,3480 2085,3515 2125.12,3555.12 Q1.DC+_6@2248.03,3555.12 ; Q2.DC+_8@2374.02,555.12 2377.29,551.84 2413.16,551.84 2570.88,394.12 3451.12,394.12 J9.4@4607,1550
DC-: C1.2 C7.2 C8.2 C9.2 C10.2 C11.2 J1.1 J9.3 Q1.DC-_1 Q1.DC-_2 Q1.DC-_3 Q1.DC-_4 Q1.DC-_5 Q1.DC-_6 Q1.DC-_7 Q1.DC-_8 Q2.DC-_1 Q2.DC-_2 Q2.DC-_3 Q2.DC-_4 Q2.DC-_5 Q2.DC-_6 Q2.DC-_7 Q2.DC-_8 R6.2 R13.2 R14.1 R15.1 R16.2 TP2.1 | length 2164.5
  Top Layer w10: Q2.DC-_8@2625.98,807.09 2697.09,807.09 2790,900 3955,900 4305,1250 J9.3@4607,1250
EGND: HS1.5 R14.2 R15.2
G_A_HS: Q2.G1_1 Q2.G1_2 U3.2A U3.4A
G_A_LS: Q2.G2_1 Q2.G2_2 U3.2B U3.4B
G_B_HS: Q1.G1_1 Q1.G1_2 U2.2A U2.4A
G_B_LS: Q1.G2_1 Q1.G2_2 U2.2B U2.4B
GND: C2.2 C3.2 C4.2 C5.2 C6.2 J3.1 J3.3 J3.4 J3.9 J3.10 R4.1 R5.1 U1.4 U4.2 | length 526.4
  Top Layer w10: C2.2@4326.42,7850 4330,7846.42 v1(4330,7805) ; C6.2@4441.42,7615 4442.37,7615 4456.24,7601.14 4456.24,7590.39 4500.58,7546.05 R5.1@4500.58,7545 v1(4545,7545) ; C3.2@4498.58,7850 4527.5,7850 ; U4.2@4529.92,7920 4529.92,7852.42 4527.5,7850 ; C4.2@4556.42,7850 4527.5,7850 ; R4.1@4615.58,7710 4668.58,7710 C5.2@4675,7716.42 4688.86,7702.56 4688.86,7671.14 v1(4690,7670) ; v1(4675,7315) 4675.23,7315.23 4675.23,7350 4686.91,7361.68 4686.91,7404.86 U1.4@4688.39,7406.34
NetC2_1: C2.1 U4.4 | length 92.8
  Top Layer w10: U4.4@4329.92,7920 4368.76,7881.16 4368.76,7863.86 4382.63,7850 C2.1@4383.58,7850
NetR1_2: R1.2 R3.1 U1.6 | length 315.4
  Top Layer w10: R1.2@4500.58,7780 R3.1@4500.58,7710 4500.58,7708.95 4522.52,7687.01 4522.52,7685.83 4531.81,7676.53 4559.92,7676.53 4586.46,7650 4629.78,7650 4661.06,7618.72 4661.06,7613.33 4661.32,7613.07 4661.32,7575.14 U1.6@4662.8,7573.66
NetR6_1: R6.1 R7.2 | length 71.5
  Top Layer w35: R7.2@280,7389.25 R6.1@280,7460.75
NetR7_1: R7.1 R8.2 | length 71.5
  Top Layer w35: R8.2@280,7089.25 R7.1@280,7160.75
NetR8_1: R8.1 R9.2 | length 71.5
  Top Layer w35: R9.2@280,6789.25 R8.1@280,6860.75
NetR10_2: R10.2 R11.1 | length 71.5
  Top Layer w35: R11.1@280,4789.25 R10.2@280,4860.75
NetR11_2: R11.2 R12.1 | length 71.5
  Top Layer w35: R12.1@280,4489.25 R11.2@280,4560.75
NetR12_2: R12.2 R13.1 | length 71.5
  Top Layer w35: R13.1@280,4189.25 R12.2@280,4260.75
NetR16_1: R16.1 R17.2 | length 71.5
  Top Layer w35: R17.2@280,1739.25 R16.1@280,1810.75
NetR17_1: R17.1 R18.2 | length 71.5
  Top Layer w35: R18.2@280,1439.25 R17.1@280,1510.75
NetR18_1: R18.1 R19.2 | length 71.5
  Top Layer w35: R19.2@280,1139.25 R18.1@280,1210.75
NTC_A+: J10.2 Q2.NTC1 | length 907.8
  Top Layer w10: Q2.NTC1@3129.92,1688.98 3190,1628.9 3190,1454.26 3644.26,1000 J10.2@3650,1000
NTC_A-: J10.1 Q2.NTC2 | length 737
  Top Layer w10: Q2.NTC2@3129.92,1562.99 3129.92,1475.08 3550,1055 J10.1@3550,1000
NTC_B+: J6.2 Q1.NTC1 | length 907.8
  Top Layer w10: Q1.NTC1@3129.92,4688.98 3190,4628.9 3190,4454.26 3644.26,4000 J6.2@3650,4000
NTC_B-: J6.1 Q1.NTC2 | length 737
  Top Layer w10: Q1.NTC2@3129.92,4562.99 3129.92,4475.08 3550,4055 J6.1@3550,4000
OUT_N: J3.7 R3.2 U1.7 | length 1502.7
  Top Layer w10: R3.2@4439.42,7710 4439.42,7708.95 4491.84,7656.53 4551.64,7656.53 4578.17,7630 4621.5,7630 4635.73,7615.77 4635.73,7575.14 U1.7@4637.2,7573.66 4638.68,7572.18 4638.68,7522.26 4712.24,7448.7 4712.24,7302.75 4657.2,7247.71 4657.2,7133.92 4601.88,7078.59 4601.88,6863.12 4631.54,6833.46 4711.54,6833.46 4740,6805 4740,6597 J3.7@4693,6550
OUT_P: J3.8 U1.1 U1.2 | length 963.2
  Top Layer w10: U1.1@4611.61,7406.34 U1.2@4637.2,7406.34 4637.2,7353.36 4633.81,7349.97 4633.81,7138.81 4580.4,7085.4 4580.4,6552.36 J3.8@4622.92,6509.84
S_A_HS: Q2.S1_1 Q2.S1_2 U3.1A U3.3A
  other v1: 1975,1685 2015,1685 1975,1725 2015,1725
S_A_LS: Q2.S2_1 Q2.S2_2 U3.1B U3.3B
  other v1: 1975,2748 2015,2748 1975,2788 2015,2788
S_B_HS: Q1.S1_1 Q1.S1_2 U2.1A U2.3A
  other v1: 1975,4685 2015,4685 1975,4725 2015,4725
S_B_LS: Q1.S2_1 Q1.S2_2 U2.1B U2.3B
  other v1: 1975,5748 2015,5748 1975,5788 2015,5788
SENSE: C3.1 R1.1 R5.2 U1.3 U4.3 | length 723.9
  Top Layer w10: U4.3@4429.92,7920 4429.92,7861.5 C3.1@4441.42,7850 4439.42,7848 R1.1@4439.42,7780 4439.42,7778.95 4417.54,7757.07 4417.07,7757.07 4406.61,7746.61 4406.61,7589.92 4415.4,7581.14 4433.56,7581.14 4439.42,7575.28 R5.2@4439.42,7545 4439.42,7543.95 4451.32,7532.04 4457.46,7532.04 4477.46,7512.04 4500,7512.04 4545,7467.04 4642.72,7467.04 4661.32,7448.45 4661.32,7407.82 U1.3@4662.8,7406.34
pads on no net: HS1.1 HS1.2 HS1.3 HS1.4 HS1.6 J3.11 MH1.1 MH2.1 Q1.2 Q2.2 U2.A46 U3.A46 U4.MH1 U4.MH2 U4.MH3 U4.MH4

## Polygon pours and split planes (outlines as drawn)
DC+ on Layer 1 "NONET_L-01_P-001" (solid, pour order 108): 2215,4300 cw(c2215,4205) 2310,4205 2310,3729.77 2394.77,3645 2394.77,2975 1730,2975 1730,1295 2215,1295 cw(c2215,1199.99) 2310.01,1199.99 2310.04,1180 2310,894.78 2394.77,810 2395.76,200 200,200 200,7990 cw(c295,7990) 295,8085 1115,8085 ccw(c1115.01,8190) 1220,8190 1220,8555 cw(c1314.99,8555.01) 1315,8650 1825.01,8650 cw(c1825.01,8555.01) 1920,8554.99 1920,4300
AC_B on Layer 1 "NONET_L-01_P-001" (solid, pour order 76): 4115,5725 cw(c4114.86,5779.86) 4060,5779.71 4060,7610 ccw(c3965.01,7610) 3965,7705 3945,7704.99 3565,7705 3450,7705 cw(c3450,7810) 3345,7810 3345,8220 ccw(c3250.07,8220) 3250.07,8314.93 2184.93,8314.93 ccw(c2184.93,8220) 2090,8220 2090,6590 ccw(c2184.99,6589.99) 2185,6495 2745,6495 cw(c2745.01,6390.01) 2850,6390 2850,5275 ccw(c2942.47,5272.47) 2940,5180 3254.86,5180 cw(c3254.88,5075.03) 3359.86,5075 3359.86,4904.86 ccw(c3454.69,4904.83) 3454.71,4810 3735,4810 cw(c3740.03,4705.03) 3845,4710 3845,3910 cw(c3745.01,3909.99) 3745,3810 2945,3810 ccw(c2944.98,3715.02) 2850,3715 2850,3464.71 ccw(c2944.83,3464.83) 2945,3370 4705.37,3370 ccw(c4705.34,3464.66) 4800,3464.71 4800,5725
GND on Layer 1 "NONET_L-01_P-001" (solid, pour order 93): 4665,8035 4375,8035 ccw(c4374.99,7940.01) 4280,7940 4280,6310 ccw(c4374.99,6309.99) 4375,6215 4665,6215 ccw(c4665,6309.94) 4759.95,6309.95 4759.95,7940.05 ccw(c4665,7940.05)
S_A_LS on Layer 1 "NONET_L-01_P-001" (solid, pour order 107): 1700,2689.71 ccw(c1744.71,2689.71) 1744.71,2645 2445,2645 2520,2570 2520,1920 2785,1655 2785,985 ccw(c2830,985) 2830,940 3130,940 ccw(c3130,985) 3175,985 3175,1105 3175,1115 ccw(c3130,1115) 3130,1160 3105,1160 cw(c3105,1215) 3050,1215 3050,1770 cw(c3105,1770) 3105,1825 3130,1825 ccw(c3130,1870) 3175,1870 3175,1970 ccw(c3130,1970) 3130,2015 2825,2015 2685,2155 2685,2735 2570,2850 1749.95,2850 1745,2850 ccw(c1745,2805) 1700,2805
S_A_HS on Layer 1 "NONET_L-01_P-001" (solid, pour order 77): 1905,2145 ccw(c1904.99,2189.99) 1950,2190 1950,2435 ccw(c1905,2435) 1905,2480 1745,2480 ccw(c1744.98,2435.02) 1700,2435 1700,535 ccw(c1745,534.99) 1745,490 1905,490 ccw(c1905,535) 1950,535 1950,810 ccw(c1905,810.01) 1905,855 cw(c1904.98,909.98) 1850,910 1850,1375 cw(c1905,1375) 1905,1430 2185,1430 ccw(c2185,1475) 2230,1475 2230,1705 ccw(c2185.02,1705.02) 2185,1750 1910,1750 1905,1750 cw(c1904.99,1804.99) 1850,1805 1850,2090 cw(c1904.99,2090)
S_B_LS on Layer 1 "NONET_L-01_P-001" (solid, pour order 101): 1700,5689.71 ccw(c1744.71,5689.71) 1744.71,5645 2445,5645 2520,5570 2520,4920 2785,4655 2785,4017.54 ccw(c2829.86,4019.86) 2832.18,3975 3130,3975 ccw(c3130,4020) 3175,4020 3175,4105 3175,4115 ccw(c3130,4115) 3130,4160 3105,4160 cw(c3105,4215) 3050,4215 3050,4770 cw(c3105,4770) 3105,4825 3130,4825 ccw(c3130,4870) 3175,4870 3175,4970 ccw(c3130.01,4970) 3130,5015 2825,5015 2685,5155 2685,5735 2570,5850 1749.95,5850 1745,5850 ccw(c1745,5805) 1700,5805
S_B_HS on Layer 1 "NONET_L-01_P-001" (solid, pour order 87): 1905,5145 ccw(c1904.99,5189.99) 1950,5190 1950,5435 ccw(c1905,5435) 1905,5480 1745,5480 ccw(c1744.98,5435.02) 1700,5435 1700,3535 ccw(c1745,3534.99) 1745,3490 1905,3490 ccw(c1905,3535) 1950,3535 1950,3810 ccw(c1905,3810.01) 1905,3855 cw(c1904.98,3909.98) 1850,3910 1850,4375 cw(c1905,4375) 1905,4430 2185,4430 ccw(c2185,4475) 2230,4475 2230,4705 ccw(c2185.02,4705.02) 2185,4750 1910,4750 1905,4750 cw(c1904.99,4804.99) 1850,4805 1850,5090 cw(c1904.99,5090)
DC- on Top Layer "NONET_L-01_P-001" (solid, pour order 109): 2385,1660 cw(c2480,1660) 2480,1755 2585,1755 cw(c2585,1660) 2680,1660 2680,295 cw(c2585,295) 2585,200 1415,200 600,200 cw(c600,295) 505,295 505,1975 ccw(c460.01,1975.01) 460,2020 215,2020 cw(c215,2055) 180,2055 180,2095 cw(c214.99,2095.01) 215,2130 460,2130 ccw(c460.96,2174.04) 505,2175 505,3825 ccw(c460.02,3825.01) 460,3870 215,3870 cw(c215,3905) 180,3905 180,3945 cw(c215,3945) 215,3980 460,3980 ccw(c460.01,4024.99) 505,4025 505,7625 ccw(c460.02,7625.02) 460,7670 195,7670 cw(c195,7685) 180,7685 180,7695 cw(c195,7695) 195,7710 460,7710 ccw(c460.01,7754.99) 505,7755 505,8555 cw(c599.99,8555.01) 600,8650 1110,8650 1145,8650 cw(c1145.03,8555.03) 1240,8555 1240,7800 ccw(c1345.08,7800.08) 1345,7695 1825,7695 cw(c1825.03,7600.03) 1920,7600 1920.01,3365 2385,3365 2385,4660 cw(c2480,4660) 2480,4755 2585,4755 cw(c2585,4660) 2680,4660 2680,3325 cw(c2585,3325) 2585,3230 1920.01,3230 1919.99,365 2385,365
G_A_LS on Top Layer "NONET_L-01_P-001" (solid, pour order 104): 1700,2689.71 ccw(c1744.71,2689.71) 1744.71,2645 2445,2645 2520,2570 2520,1920 2785,1655 2785,985 ccw(c2830,985) 2830,940 3130,940 ccw(c3130,985) 3175,985 3175,1105 3175,1115 ccw(c3130,1115) 3130,1160 3105,1160 cw(c3105,1215) 3050,1215 3050,1770 cw(c3105,1770) 3105,1825 3130,1825 ccw(c3130,1870) 3175,1870 3175,1970 ccw(c3130,1970) 3130,2015 2825,2015 2685,2155 2685,2735 2570,2850 1749.95,2850 1745,2850 ccw(c1745,2805) 1700,2805
G_A_HS on Top Layer "NONET_L-01_P-001" (solid, pour order 82): 1904.99,2144.99 ccw(c1904.99,2189.99) 1950,2190 1950,2435 ccw(c1905,2435) 1905,2480 1745,2480 ccw(c1744.98,2435.02) 1700,2435 1700,535 ccw(c1744.99,534.99) 1745,490 1905,490 ccw(c1905,534.99) 1950,535 1950,810 ccw(c1905.01,810.01) 1905,855 cw(c1904.98,909.98) 1850,910 1850,1375 cw(c1905,1375) 1905,1430 2185,1430 ccw(c2185,1475) 2230,1475 2230,1605 ccw(c2185.02,1605.02) 2185,1650 1845,1650 cw(c1844.99,1704.99) 1790,1705 1790,1730 cw(c1825,1730) 1825,1765 ccw(c1825,1790) 1850,1790 1850,2090 cw(c1904.99,2090)
G_B_LS on Top Layer "NONET_L-01_P-001" (solid, pour order 106): 1700,5689.71 ccw(c1744.71,5689.71) 1744.71,5645 2445,5645 2520,5570 2520,4920 2785,4655 2785,4020 ccw(c2830,4020) 2830,3975 3130,3975 ccw(c3130,4020) 3175,4020 3175,4105 3175,4115 ccw(c3130,4115) 3130,4160 3105,4160 cw(c3105,4215) 3050,4215 3050,4770 cw(c3105,4770) 3105,4825 3130,4825 ccw(c3130,4870) 3175,4870 3175,4970 ccw(c3130.01,4970) 3130,5015 2825,5015 2685,5155 2685,5735 2570,5850 1749.95,5850 1745,5850 ccw(c1745,5805) 1700,5805
AC_B on Top Layer "NONET_L-01_P-001" (solid, pour order 99): 4115,5725 cw(c4114.86,5779.86) 4060,5779.71 4060,7610 ccw(c3965.01,7610) 3965,7705 3945,7704.99 3565,7705 3450,7705 cw(c3450,7810) 3345,7810 3345,8220 ccw(c3250.07,8220) 3250.07,8314.93 2184.93,8314.93 ccw(c2184.93,8220) 2090,8220 2090,6590 ccw(c2184.99,6589.99) 2185,6495 2745,6495 cw(c2745.01,6390.01) 2850,6390 2850,5275 ccw(c2942.47,5272.47) 2940,5180 3254.86,5180 cw(c3254.88,5075.03) 3359.86,5075 3359.86,4904.86 ccw(c3454.69,4904.83) 3454.71,4810 3735,4810 cw(c3740.03,4705.03) 3845,4710 3845,3910 cw(c3745.01,3909.99) 3745,3810 2945,3810 ccw(c2944.98,3715.02) 2850,3715 2850,3464.71 ccw(c2944.83,3464.83) 2945,3370 4705.37,3370 ccw(c4705.34,3464.66) 4800,3464.71 4800,5725
G_B_HS on Top Layer "NONET_L-01_P-001" (solid, pour order 90): 1904.99,5144.99 ccw(c1904.99,5189.99) 1950,5190 1950,5435 ccw(c1905,5435) 1905,5480 1745,5480 ccw(c1744.98,5435.02) 1700,5435 1700,3535 ccw(c1744.99,3534.99) 1745,3490 1905,3490 ccw(c1905,3534.99) 1950,3535 1950,3810 ccw(c1905.01,3810.01) 1905,3855 cw(c1904.98,3909.98) 1850,3910 1850,4375 cw(c1905,4375) 1905,4430 2185,4430 ccw(c2185,4475) 2230,4475 2230,4605 ccw(c2185.02,4605.02) 2185,4650 1845,4650 cw(c1844.99,4704.99) 1790,4705 1790,4730 cw(c1825,4730) 1825,4765 ccw(c1825,4790) 1850,4790 1850,5090 cw(c1904.99,5090)
S_A_LS on Top Layer "NONET_L-01_P-001" (solid, pour order 98): 1805,2768 ccw(c1845,2768) 1845,2728 2189.63,2728 ccw(c2189.81,2768.19) 2230,2768 ccw(c2187.34,2770.3) 2189.63,2812.96 1849.96,2812.96 ccw(c1849.95,2768.01)
EGND on Top Layer "NONET_L-01_P-001" (solid, pour order 97): 320,3700 cw(c320,3675) 345,3675 345,2325 cw(c320,2325) 320,2300 240,2300 cw(c240,2325) 215,2325 215,3675 cw(c240,3675) 240,3700
S_B_LS on Top Layer "NONET_L-01_P-001" (solid, pour order 94): 1805,5768 ccw(c1845,5768) 1845,5728 2189.63,5728 ccw(c2189.81,5768.19) 2230,5768 ccw(c2187.34,5770.3) 2189.63,5812.96 1849.96,5812.96 ccw(c1849.95,5768.01)
S_B_HS on Top Layer "NONET_L-01_P-001" (solid, pour order 91): 1805,4705 ccw(c1845,4705) 1845,4665 2189.63,4665 ccw(c2189.81,4705.19) 2230,4705 ccw(c2187.34,4707.3) 2189.63,4749.96 1849.96,4749.96 ccw(c1849.95,4705.01)
S_A_HS on Top Layer "NONET_L-01_P-001" (solid, pour order 89): 1805,1705 ccw(c1845,1705) 1845,1665 2189.63,1665 ccw(c2189.81,1705.19) 2230,1705 ccw(c2187.34,1707.3) 2189.63,1749.96 1849.96,1749.96 ccw(c1849.95,1705.01)
AC_A on Layer 2 "NONET_L-01_P-001" (solid, pour order 115): 4800,2655 ccw(c4705,2655) 4705,2750 4650,2750 3000,2750 2945,2750 ccw(c2945,2655) 2850,2655 2850,2600 2850,2274.99 ccw(c2944.96,2274.96) 2945,2180 3254.86,2180 cw(c3254.9,2075.04) 3359.86,2075 3359.86,1904.86 ccw(c3454.67,1904.81) 3454.71,1810 3735,1810 cw(c3740.05,1705.05) 3845,1710 3845,910 cw(c3745.02,909.98) 3745,810 2945,810 ccw(c2944.97,715.03) 2850,715 2850,535 ccw(c2944.95,534.95) 2945,440 3927.35,440 ccw(c3941.34,928.66) 4430,914.72 4430,1620 cw(c4534.99,1620.01) 4535,1725 4700,1725 ccw(c4700.02,1824.98) 4800,1825
DC- on Layer 2 "NONET_L-01_P-001" (solid, pour order 112): 1920,7430 1920,7590 ccw(c1825,7590) 1825,7685 1700,7685 1385.07,7685 cw(c1384.99,7789.99) 1280,7789.93 1280,7825 1280,8555 ccw(c1185,8555) 1185,8650 1115,8650 200,8650 200,200 2560,200 2585,200 ccw(c2585,295) 2680,295 2680,6235 ccw(c2585.01,6235) 2585.01,6329.99 2025,6330.01 cw(c2025,6435) 1920,6435
AC_B on Layer 2 "NONET_L-01_P-001" (solid, pour order 105): 4115,5725 cw(c4114.86,5779.86) 4060,5779.71 4060,7610 ccw(c3965.01,7610) 3965,7705 3945,7704.99 3565,7705 3450,7705 cw(c3450,7810) 3345,7810 3345,8220 ccw(c3250.07,8220) 3250.07,8314.93 2184.93,8314.93 ccw(c2184.93,8220) 2090,8220 2090,6590 ccw(c2184.99,6589.99) 2185,6495 2745,6495 cw(c2745.01,6390.01) 2850,6390 2850,5275 ccw(c2942.47,5272.47) 2940,5180 3254.86,5180 cw(c3254.88,5075.03) 3359.86,5075 3359.86,4904.86 ccw(c3454.69,4904.83) 3454.71,4810 3735,4810 cw(c3740.03,4705.03) 3845,4710 3845,3910 cw(c3745.01,3909.99) 3745,3810 2945,3810 ccw(c2944.98,3715.02) 2850,3715 2850,3464.71 ccw(c2944.83,3464.83) 2945,3370 4705.37,3370 ccw(c4705.34,3464.66) 4800,3464.71 4800,5725
+5V on Layer 2 "NONET_L-01_P-001" (solid, pour order 85): 4665,8035 4375,8035 ccw(c4374.99,7940.01) 4280,7940 4280,6310 ccw(c4374.99,6309.99) 4375,6215 4665,6215 ccw(c4665,6309.94) 4759.95,6309.95 4759.95,7940.05 ccw(c4665,7940.05)
+5V on Layer 2 "NONET_L-01_P-001" (solid, pour order 84): 4665,8035 4375,8035 ccw(c4374.99,7940.01) 4280,7940 4280,6310 ccw(c4374.99,6309.99) 4375,6215 4665,6215 ccw(c4665,6309.94) 4759.95,6309.95 4759.95,7940.05 ccw(c4665,7940.05)
AC_A on Layer 3 "NONET_L-01_P-001" (solid, pour order 110): 3845,3910 cw(c3745.02,3909.98) 3745,3810 3420,3810 ccw(c3420,3715.41) 3325.41,3715.41 3325,3715 3325,3465 cw(c3220.01,3464.99) 3220,3360 2945,3360 ccw(c2945,3265.02) 2850,3265 2850,2274.99 ccw(c2944.97,2274.97) 2945,2180 3254.85,2180 cw(c3254.89,2075.03) 3359.86,2075 3359.86,1904.86 ccw(c3454.68,1904.82) 3454.71,1810 3735,1810 cw(c3740.04,1705.04) 3845,1710 3845,910 cw(c3745.02,909.98) 3745,810 2945,810 ccw(c2944.98,715.03) 2850,715 2850,535 ccw(c2944.96,534.96) 2945,440 3927.35,440 ccw(c3941.34,928.66) 4430,914.72 4430,1620 cw(c4534.99,1620) 4535,1725 4700,1725 ccw(c4700.02,1824.98) 4800,1825 4800,4110 4800,5725 4115,5725 cw(c4115,5780) 4060,5779.99 4060,8219.99 ccw(c3965,8220) 3965.01,8315 2945,8315 ccw(c2945,8220) 2850,8220 2850.01,5741.01 ccw(c2944.97,5739.97) 2945,5645 3249.86,5645 cw(c3249.88,5535.03) 3359.86,5535 3359.86,4904.86 ccw(c3454.68,4904.83) 3454.71,4810 3740,4810 cw(c3740.03,4705.03) 3845,4705
GND on Layer 3 "NONET_L-01_P-001" (solid, pour order 102): 4665,8035 4375,8035 ccw(c4374.99,7940.01) 4280,7940 4280,6310 ccw(c4374.99,6309.99) 4375,6215 4665,6215 ccw(c4665,6309.94) 4759.95,6309.95 4759.95,7940.05 ccw(c4665,7940.05)
AC_A on Layer 4 "NONET_L-01_P-001" (solid, pour order 111): 3845,3910 cw(c3745.02,3909.98) 3745,3810 3420,3810 ccw(c3420,3715.41) 3325.41,3715.41 3325,3715 3325,3465 cw(c3220.01,3464.99) 3220,3360 2945,3360 ccw(c2945,3265.02) 2850,3265 2850,2274.99 ccw(c2944.97,2274.97) 2945,2180 3254.85,2180 cw(c3254.89,2075.03) 3359.86,2075 3359.86,1904.86 ccw(c3454.68,1904.82) 3454.71,1810 3735,1810 cw(c3740.04,1705.04) 3845,1710 3845,910 cw(c3745.02,909.98) 3745,810 2945,810 ccw(c2944.98,715.03) 2850,715 2850,535 ccw(c2944.96,534.96) 2945,440 3927.35,440 ccw(c3941.34,928.66) 4430,914.72 4430,1620 cw(c4534.99,1620) 4535,1725 4700,1725 ccw(c4700.02,1824.98) 4800,1825 4800,4110 4800,5725 4115,5725 cw(c4115,5780) 4060,5779.99 4060,8219.99 ccw(c3965,8220) 3965.01,8315 2945,8315 ccw(c2945,8220) 2850,8220 2850.01,5741.01 ccw(c2944.97,5739.97) 2945,5645 3249.86,5645 cw(c3249.88,5535.03) 3359.86,5535 3359.86,4904.86 ccw(c3454.68,4904.83) 3454.71,4810 3740,4810 cw(c3740.03,4705.03) 3845,4705
DC- on Layer 4 "NONET_L-01_P-001" (solid, pour order 113): 1920,7430 1920,7590 ccw(c1825,7590) 1825,7685 1700,7685 1385.07,7685 cw(c1384.99,7789.99) 1280,7789.93 1280,7825 1280,8555 ccw(c1185,8555) 1185,8650 1115,8650 200,8650 200,200 2560,200 2585,200 ccw(c2585,295) 2680,295 2680,6235 ccw(c2585.01,6235) 2585.01,6329.99 2025,6330.01 cw(c2025,6435) 1920,6435
+5V on Layer 4 "NONET_L-01_P-001" (solid, pour order 103): 4665,8035 4375,8035 ccw(c4374.99,7940.01) 4280,7940 4280,6310 ccw(c4374.99,6309.99) 4375,6215 4665,6215 ccw(c4665,6309.94) 4759.95,6309.95 4759.95,7940.05 ccw(c4665,7940.05)
DC+ on Bottom Layer "NONET_L-01_P-001" (solid, pour order 114): 2680,4975 cw(c2585.01,4974.99) 2585,4880 2415,4880 ccw(c2414.99,4775.01) 2310,4775 2310,3720.25 ccw(c2415.25,3720.25) 2415.25,3615 2583.66,3615 cw(c2584.92,3519.92) 2680,3521.18 2680,2385 2680,1975 cw(c2585.01,1974.99) 2585,1880 2415,1880 ccw(c2414.99,1775.01) 2310,1775 2310,720.02 ccw(c2415,720) 2414.99,615 2585,615 cw(c2585.01,520.01) 2680,520 2680,500 2680,285 cw(c2595.04,284.96) 2595,200 200,200 200,7600 cw(c295,7600) 295,7695 1145,7695 ccw(c1145,7800) 1250,7800 1250,8555 cw(c1345,8555) 1345,8650 1825,8650 cw(c1825.02,8555.02) 1920,8555 1920,6435 ccw(c2024.99,6434.99) 2025,6330 2585,6330 cw(c2585.02,6235.02) 2680,6235 2680,5385
AC_A on Bottom Layer "NONET_L-01_P-001" (solid, pour order 116): 2945,2750 ccw(c2945,2655) 2850,2655 2850,2274.99 ccw(c2944.96,2274.96) 2945,2180 3254.86,2180 cw(c3254.9,2075.04) 3359.86,2075 3359.86,1904.86 ccw(c3454.67,1904.81) 3454.71,1810 3735,1810 cw(c3740.04,1705.05) 3845,1710 3845,910 cw(c3745.02,909.98) 3745,810 2945,810 ccw(c2944.97,715.03) 2850,715 2850,535 ccw(c2944.96,534.96) 2945,440 4305,440 ccw(c4305.01,534.99) 4400,534.98 4400,1105 4400,1610 4400,1700 cw(c4460,1700) 4460,1760 4705,1760 ccw(c4705,1855) 4800,1855 4800,2750

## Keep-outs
Top Layer:
  rectangle: 2845,5455 2885,5760
  rectangle: 1181.15,1495 1280,1875
  rectangle: 1181.15,4495 1280,4875
  lines w10: 598,8555 cw(c698,8555) 698,8655 ; 600,295 ccw(c700,295) 700,195 ; 1445,1228 cw(c1445,1128) 1545,1128 ; 1445,2070 ccw(c1445,2170) 1545,2170 ; 1445,2330 cw(c1445,2230) 1545,2230 ; 1445,4228 cw(c1445,4128) 1545,4128 ; 1445,5070 ccw(c1445,5170) 1545,5170 ; 1445,5330 cw(c1445,5230) 1545,5230 ; 1825,6225 ccw(c1825,6325) 1925,6325 ; 3840,4019.91 cw(c3940,4019.91) 3940,4119.91 ; 3840,4697 ccw(c3940,4697) 3940,4597 ; 3965,6265 ccw(c3965,6365) 4065,6365 ; 4037.95,5787.39 cw(c4031,5748) 4068.59,5761.68 ; 4355,5730 cw(c4355,5680) 4401.99,5697.1 ; 4755,5398 cw(c4755,5348) 4805,5348
Layer 1:
  circle w15: c1499,1875 r47.17
  circle w15: c1381,1875 r47.17
  circle w15: c1499,4875 r47.17
  circle w15: c1381,4875 r47.17
  rectangle: 1383.02,4718.63 1590,4930
  rectangle: 1383.02,1718.63 1590,1930
  rectangle: 715,5295 1035,5510
  rectangle: 715,2695 1035,2910
  rectangle: 1380,1820 1500,1930
  rectangle: 1380,4820 1500,4930
  lines w10: 195,665 ccw(c295,665) 295,565 ; 195,2585 cw(c295,2585) 295,2685 ; 195,3415 ccw(c295,3415) 295,3315 ; 195,5335 cw(c295,5335) 295,5435 ; 195,6165 ccw(c295,6165) 295,6065 ; 565,275 ccw(c645,275) 645,195 ccw(c645,275) 725,275 ; 1030,295 ccw(c1130,295) 1130,195 ; 1479,1925 ccw(c1479,2025) 1579,2025 ; 1479,2365 cw(c1479,2265) 1579,2265 ; 1479,2685 ccw(c1479,2785) 1579,2785 ; 1479,4925 ccw(c1479,5025) 1579,5025 ; 1479,5365 cw(c1479,5265) 1579,5265 ; 1479,5685 ccw(c1479,5785) 1579,5785 ; 1971,1200 cw(c2071,1200) 2071,1300 ; 1971,4205 cw(c2071,4205) 2071,4305 ; 2071,670 ccw(c2171,670) 2171,570 ; 2071,3670 ccw(c2171,3670) 2171,3570 ; 2300,195 ccw(c2300,295) 2400,295 ; 2300,2971 ccw(c2300,3071) 2400,3071 ; 3840,4055 cw(c3940,4055) 3940,4155 ; 3840,4661.91 ccw(c3940,4661.91) 3940,4561.91 ; 3965,6231 ccw(c3965,6331) 4065,6331 ; 4025,5820 cw(c4025,5780) 4065,5780 ; 4275,6945.79 cw(c4375,6945.79) 4375,7045.79 ; 4275,7595 ccw(c4375,7595) 4375,7495 ; 4365,5730 cw(c4365,5650) 4443.79,5663.89 ; 4705,5435 cw(c4705,5335) 4805,5335
Layer 4:
  rectangle: 2135,4730 2190,4840
  rectangle: 2135,1730 2190,1840
  region: 1035,4210 715,4210 715,3995 1035,3995
  region: 1035,1610 715,1610 715,1395 1035,1395
  region: 1035,6810 715,6810 715,6595 1035,6595
  rectangle: 2830,7045 2880,7495
  region: 1664.78,4875 1215.22,4875 1183.01,4546.5 1730.37,4546.5
  region: 1664.78,1875 1215.22,1875 1183.01,1546.5 1730.37,1546.5
  lines w10: 195,638 ccw(c265,638) 265,568 ; 195,650 cw(c265,650) 265,720 ; 195,1100 ccw(c295,1100) 295,1000 ; 195,2585 cw(c295,2585) 295,2685 ; 195,3415 ccw(c295,3415) 295,3315 ; 195,4900 cw(c295,4900) 295,5000 ; 195,5350 ccw(c265,5350) 265,5280 ; 195,5362 cw(c265,5362) 265,5432 ; 195,6165 ccw(c295,6165) 295,6065 ; 195,6270 cw(c295,6270) 295,6370 ; 195,6750 ccw(c295,6750) 295,6650 ; 195,8085 cw(c295,8085) 295,8185 ; 565,295 ccw(c665,295) 665,195 ; 565,8555 cw(c665,8555) 665,8655 ; 1835,1685 1845,1950 ; 1835,4685 1845,4950 ; 2148,1640 2273,1920 ; 2148,4640 2273,4920 ; 2845,6970.79 cw(c2945,6970.79) 2945,7070.79 ; 2845,7570 ccw(c2945,7570) 2945,7470 ; 3840,1055 cw(c3940,1055) 3940,1155 ; 3840,1661.91 ccw(c3940,1661.91) 3940,1561.91 ; 3840,4055 cw(c3940,4055) 3940,4155 ; 3840,4661.91 ccw(c3940,4661.91) 3940,4561.91 ; 3965,6231 ccw(c3965,6331) 4065,6331 ; 4025,5820 cw(c4025,5780) 4065,5780 ; 4275,6945.79 cw(c4375,6945.79) 4375,7045.79 ; 4275,7595 ccw(c4375,7595) 4375,7495 ; 4365,5730 cw(c4365,5650) 4443.79,5663.89 ; 4705,2685 cw(c4705,2585) 4805,2585 ; 4705,3315 ccw(c4705,3415) 4805,3415 ; 4705,5435 cw(c4705,5335) 4805,5335
Layer 2:
  region: 1035,1610 715,1610 715,1395 1035,1395
  region: 1035,4210 715,4210 715,3995 1035,3995
  region: 1035,6810 715,6810 715,6595 1035,6595
  region: 1664.78,1875 1215.22,1875 1183.01,1546.5 1730.37,1546.5
  region: 1664.78,4875 1215.22,4875 1183.01,4546.5 1730.37,4546.5
  lines w10: 195,638 ccw(c265,638) 265,568 ; 195,650 cw(c265,650) 265,720 ; 195,1100 ccw(c295,1100) 295,1000 ; 195,2585 cw(c295,2585) 295,2685 ; 195,3415 ccw(c295,3415) 295,3315 ; 195,4900 cw(c295,4900) 295,5000 ; 195,5350 ccw(c265,5350) 265,5280 ; 195,5362 cw(c265,5362) 265,5432 ; 195,6165 ccw(c295,6165) 295,6065 ; 195,6270 cw(c295,6270) 295,6370 ; 195,6750 ccw(c295,6750) 295,6650 ; 195,8085 cw(c295,8085) 295,8185 ; 565,295 ccw(c665,295) 665,195 ; 565,8555 cw(c665,8555) 665,8655 ; 3840,1055 cw(c3940,1055) 3940,1155 ; 3840,1661.91 ccw(c3940,1661.91) 3940,1561.91 ; 3840,4055 cw(c3940,4055) 3940,4155 ; 3840,4661.91 ccw(c3940,4661.91) 3940,4561.91 ; 3965,6231 ccw(c3965,6331) 4065,6331 ; 4025,5820 cw(c4025,5780) 4065,5780 ; 4275,6945.79 cw(c4375,6945.79) 4375,7045.79 ; 4275,7595 ccw(c4375,7595) 4375,7495 ; 4365,5730 cw(c4365,5650) 4443.79,5663.89 ; 4705,2685 cw(c4705,2585) 4805,2585 ; 4705,5435 cw(c4705,5335) 4805,5335
Layer 3:
  rectangle: 2830,7045 2880,7495
  lines w10: 2845,6970.79 cw(c2945,6970.79) 2945,7070.79 ; 2845,7570 ccw(c2945,7570) 2945,7470 ; 3840,1055 cw(c3940,1055) 3940,1155 ; 3840,1661.91 ccw(c3940,1661.91) 3940,1561.91 ; 3840,4055 cw(c3940,4055) 3940,4155 ; 3840,4661.91 ccw(c3940,4661.91) 3940,4561.91 ; 3965,6231 ccw(c3965,6331) 4065,6331 ; 4025,5820 cw(c4025,5780) 4065,5780 ; 4275,6945.79 cw(c4375,6945.79) 4375,7045.79 ; 4275,7595 ccw(c4375,7595) 4375,7495 ; 4365,5730 cw(c4365,5650) 4443.79,5663.89 ; 4705,2685 cw(c4705,2585) 4805,2585 ; 4705,3315 ccw(c4705,3415) 4805,3415 ; 4705,5435 cw(c4705,5335) 4805,5335
Bottom Layer:
  rectangle: 2435.49,1870 2704.51,2192.91
  rectangle: 2435.49,4870 2704.51,5192.91
  rectangle: 1575,2290 1625,2465
  rectangle: 1635,2245 1685,2420
  rectangle: 1580,2585 1695,2760
  rectangle: 1660,2535 1775,2805
  rectangle: 1740,2605 1855,2845
  rectangle: 2049.79,2417.5 2099.79,2592.5
  rectangle: 2080,2521.22 2130,2630
  rectangle: 2080,5521.22 2130,5630
  rectangle: 2049.79,5417.5 2099.79,5592.5
  rectangle: 1740,5605 1855,5845
  rectangle: 1660,5535 1775,5805
  rectangle: 1580,5585 1695,5760
  rectangle: 1635,5245 1685,5420
  rectangle: 1575,5290 1625,5465
  lines w10: 195,700 ccw(c295,700) 295,600 ; 195,2550 cw(c295,2550) 295,2650 ; 195,3450 ccw(c295,3450) 295,3350 ; 195,5300 cw(c295,5300) 295,5400 ; 195,6200 ccw(c295,6200) 295,6100 ; 602,245 ccw(c652,245) 652,195 ; 645,195 ccw(c645,245) 695,245 ; 1065,295 ccw(c1165,295) 1165,195 ; 1505,2330 1735,2195 ; 1505,5330 1735,5195 ; 1515,2715 1885,2935 ; 1515,5715 1885,5935 ; 2050,2275 2175,2680 ; 2050,5275 2175,5680 ; 2315,1775 cw(c2415,1775) 2415,1875 ; 2390,1872 ccw(c2390,1922) 2440,1922 ; 2390,4872 ccw(c2390,4922) 2440,4922 ; 2585,3620 cw(c2585,3520) 2685,3520 ; 2602.36,2376.52 ccw(c2585,2475) 2685,2475 ; 2602.36,5376.52 ccw(c2585,5475) 2685,5475 ; 3840,1019.91 cw(c3940,1019.91) 3940,1119.91 ; 3840,1697 ccw(c3940,1697) 3940,1597 ; 4705,2650 cw(c4705,2550) 4805,2550

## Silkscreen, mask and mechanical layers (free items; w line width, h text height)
Top Overlay:
  drawing of 107 lines, arcs and shapes, not listed
  text "-" at 851.31,8012.98 h400
  text "+" at 1515.57,7978.53 h400
  text "B" at 2264.58,7550 h400
  text "A" at 3580.21,7550 h400
  text "+" at 1653.48,7329.71 h180
  text "-" at 1653.48,7064.71 h180
  text "A" at 4231.52,3494.71 h180
  text "B" at 4476.52,3494.71 h180
  text "WOLFPACK 60KW DAB (INPUT STAGE) / PN CRD60DD12N-GMA, V1 10/2023" at 1163.05,55 h180
Mechanical 1:
  rectangle: 0,3500 5000,8500
Board Outline:
  the board outline again, w1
